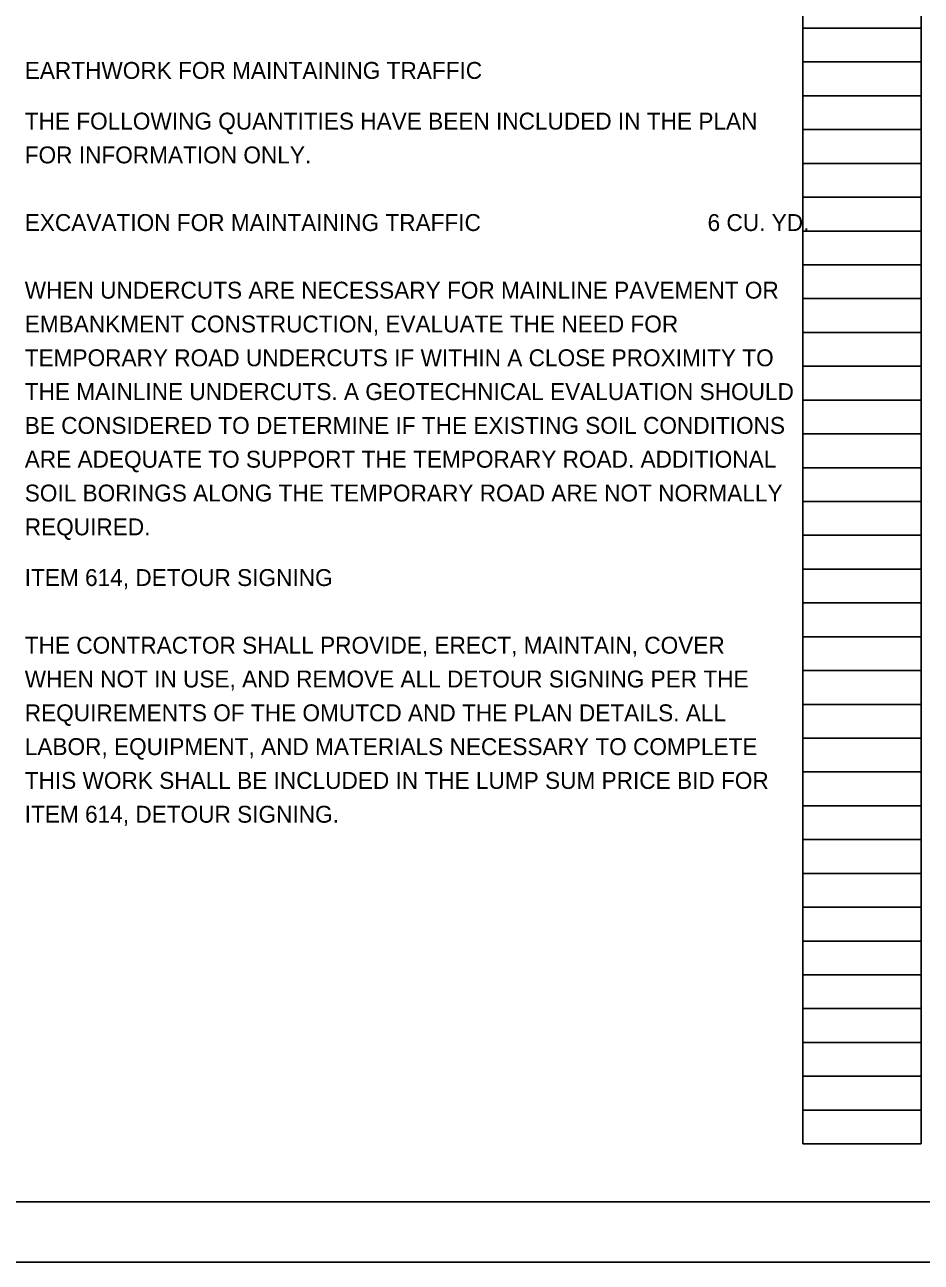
# Model space of a CAD drawing. Extents: x 0 to 34, y 0 to 33.4.
# Drawn here: x 17.24 to 24.66, y 0 to 10.25 of the extents above; entities that cross this region are included whole.
import ezdxf

# ---------------------------------------------------------------- set-up
doc = ezdxf.new("R2010")
doc.units = 0
for name, color, linetype in [('SH_Border', 7, 'Continuous'), ('SH_Cut_Line', 7, 'Continuous'), ('SH_Data', 7, 'Continuous'), ('TX_X_20', 7, 'Continuous')]:
    doc.layers.add(name, color=color, linetype=linetype)

msp = doc.modelspace()

# ---------------------------------------------------------------- linework, layer by layer
at = {"layer": 'SH_Border'}
msp.add_lwpolyline([(1.5, 21.5), (33.5, 21.5), (33.5, 0.5), (1.5, 0.5)], close=True, dxfattribs=at)
at = {"layer": 'SH_Cut_Line'}
msp.add_lwpolyline([(0, 0), (34, 0), (34, 22), (0, 22)], close=True, dxfattribs=at)
at = {"layer": 'SH_Data'}
for p, q in [((23.68, 0.98), (23.68, 21.14)), ((24.66, 0.98), (24.66, 21.14)), ((23.68, 10.22), (24.66, 10.22)), ((23.68, 9.94), (24.66, 9.94)), ((23.68, 9.66), (24.66, 9.66)), ((23.68, 9.38), (24.66, 9.38)), ((23.68, 9.1), (24.66, 9.1)), ((23.68, 8.82), (24.66, 8.82)), ((23.68, 8.54), (24.66, 8.54)), ((23.68, 8.26), (24.66, 8.26)), ((23.68, 7.98), (24.66, 7.98)), ((23.68, 7.7), (24.66, 7.7)), ((23.68, 7.42), (24.66, 7.42)), ((23.68, 7.14), (24.66, 7.14)), ((23.68, 6.86), (24.66, 6.86)), ((23.68, 6.58), (24.66, 6.58)), ((23.68, 6.3), (24.66, 6.3)), ((23.68, 6.02), (24.66, 6.02)), ((23.68, 5.74), (24.66, 5.74)), ((23.68, 5.46), (24.66, 5.46)), ((23.68, 5.18), (24.66, 5.18)), ((23.68, 4.9), (24.66, 4.9)), ((23.68, 4.62), (24.66, 4.62)), ((23.68, 4.34), (24.66, 4.34)), ((23.68, 4.06), (24.66, 4.06)), ((23.68, 3.78), (24.66, 3.78)), ((23.68, 3.5), (24.66, 3.5)), ((23.68, 3.22), (24.66, 3.22)), ((23.68, 2.94), (24.66, 2.94)), ((23.68, 2.66), (24.66, 2.66)), ((23.68, 2.38), (24.66, 2.38)), ((23.68, 2.1), (24.66, 2.1)), ((23.68, 1.82), (24.66, 1.82)), ((23.68, 1.54), (24.66, 1.54)), ((23.68, 1.26), (24.66, 1.26)), ((23.68, 0.98), (24.66, 0.98))]:
    msp.add_line(p, q, dxfattribs=at)

# ---------------------------------------------------------------- texts
at = {"layer": 'TX_X_20'}
for s, p in [('EARTHWORK FOR MAINTAINING TRAFFIC', (17.24, 9.8)), ('THE FOLLOWING QUANTITIES HAVE BEEN INCLUDED IN THE PLAN', (17.24, 9.38)), ('FOR INFORMATION ONLY.', (17.24, 9.1)), ('EXCAVATION FOR MAINTAINING TRAFFIC     ', (17.24, 8.54)), (' 6 CU. YD.', (22.84, 8.54)), ('WHEN UNDERCUTS ARE NECESSARY FOR MAINLINE PAVEMENT OR ', (17.24, 7.98)), ('EMBANKMENT CONSTRUCTION, EVALUATE THE NEED FOR', (17.24, 7.7)), ('TEMPORARY ROAD UNDERCUTS IF WITHIN A CLOSE PROXIMITY TO ', (17.24, 7.42)), ('THE MAINLINE UNDERCUTS. A GEOTECHNICAL EVALUATION SHOULD ', (17.24, 7.14)), ('BE CONSIDERED TO DETERMINE IF THE EXISTING SOIL CONDITIONS ', (17.24, 6.86)), ('ARE ADEQUATE TO SUPPORT THE TEMPORARY ROAD. ADDITIONAL ', (17.24, 6.58)), ('SOIL BORINGS ALONG THE TEMPORARY ROAD ARE NOT NORMALLY ', (17.24, 6.3)), ('REQUIRED.', (17.24, 6.02)), ('ITEM 614, DETOUR SIGNING', (17.24, 5.6)), ('THE CONTRACTOR SHALL PROVIDE, ERECT, MAINTAIN, COVER ', (17.24, 5.04)), ('WHEN NOT IN USE, AND REMOVE ALL DETOUR SIGNING PER THE ', (17.24, 4.76)), ('REQUIREMENTS OF THE OMUTCD AND THE PLAN DETAILS. ALL ', (17.24, 4.48)), ('LABOR, EQUIPMENT, AND MATERIALS NECESSARY TO COMPLETE ', (17.24, 4.2)), ('THIS WORK SHALL BE INCLUDED IN THE LUMP SUM PRICE BID FOR ', (17.24, 3.92)), ('ITEM 614, DETOUR SIGNING.', (17.24, 3.64))]:
    msp.add_text(s, height=0.14, dxfattribs=at).set_placement(p)

doc.saveas('drawing.dxf')
